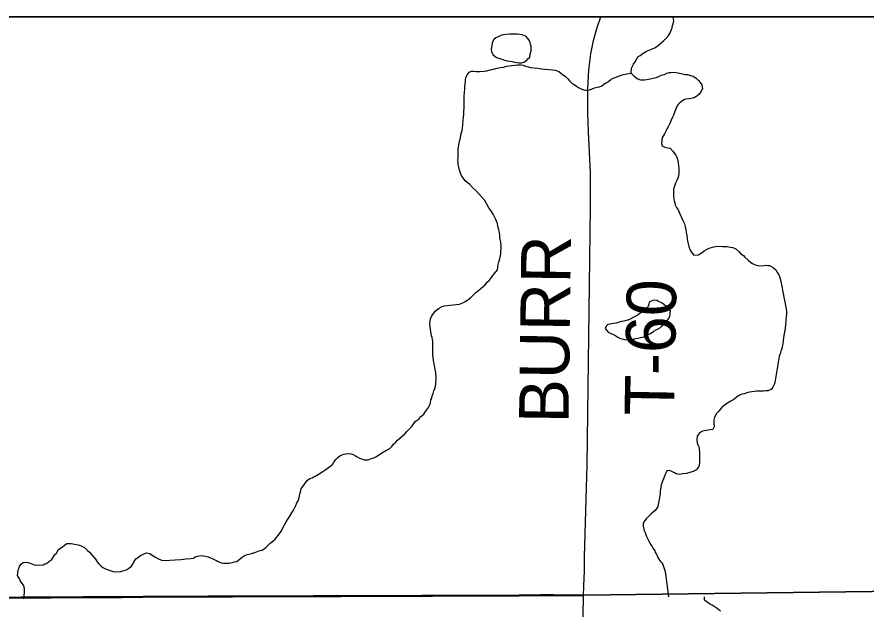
# Model space of a CAD drawing. Extents: x 0 to 34, y 0 to 22.
# Drawn here: x 3.195 to 4.168, y 20.221 to 20.9 of the extents above; entities that cross this region are included whole.
import ezdxf

# ---------------------------------------------------------------- set-up
doc = ezdxf.new("R2010")
doc.units = 0
for name, color, linetype in [('GM_X_Corporation', 7, 'Continuous'), ('GM_X_Minor_Lake', 7, 'Continuous'), ('GM_X_Minor_River', 7, 'Continuous'), ('GM_X_Township_Road', 7, 'Continuous'), ('GM_X_Township_Road_Text', 7, 'Continuous'), ('SH_Data', 7, 'Continuous')]:
    doc.layers.add(name, color=color, linetype=linetype)

msp = doc.modelspace()

# ---------------------------------------------------------------- linework, layer by layer
at = {"layer": 'GM_X_Corporation'}
for points in [[(7.88526, 20.89996), (2.1, 20.89996)], [(7.88526, 20.89996), (2.67133, 20.89996)], [(4.23527, 20.24193), (3.84431, 20.23677), (3.83537, 20.23691), (3.82602, 20.23702), (3.81005, 20.23712), (3.79513, 20.23712), (3.77046, 20.23676), (3.75805, 20.23671), (3.74563, 20.23667), (3.72077, 20.23656), (3.67105, 20.23646), (3.65864, 20.2364), (3.61523, 20.23629), (3.60009, 20.23626), (3.56599, 20.23605), (3.53492, 20.23598), (3.50078, 20.23579), (3.47907, 20.23578), (3.45731, 20.23576), (3.44179, 20.23571), (3.42316, 20.23562), (3.41385, 20.23562), (3.37656, 20.23558), (3.34551, 20.23546), (3.33933, 20.23533), (3.31461, 20.23489), (3.29289, 20.23498), (3.27112, 20.23493), (3.23381, 20.23452), (3.19962, 20.23446), (3.1561, 20.23368)], [(3.1561, 20.23368), (3.19962, 20.23446), (3.23381, 20.23452), (3.27112, 20.23493), (3.29289, 20.23498), (3.31461, 20.23489), (3.33933, 20.23533), (3.34551, 20.23546), (3.37656, 20.23558), (3.41385, 20.23562), (3.42316, 20.23562), (3.44179, 20.23571), (3.45731, 20.23576), (3.47907, 20.23578), (3.50078, 20.23579), (3.53492, 20.23598), (3.56599, 20.23605), (3.60009, 20.23626), (3.61523, 20.23629), (3.65864, 20.2364), (3.67105, 20.23646), (3.72077, 20.23656), (3.74563, 20.23667), (3.75805, 20.23671), (3.77046, 20.23676), (3.79513, 20.23712), (3.81005, 20.23712), (3.82602, 20.23702), (3.83537, 20.23691), (3.84431, 20.23677), (4.23527, 20.24193)], [(4.23527, 20.24193), (3.84431, 20.23677), (3.83537, 20.23691), (3.82602, 20.23702), (3.81005, 20.23712), (3.79513, 20.23712), (3.77046, 20.23676), (3.75805, 20.23671), (3.74563, 20.23667), (3.72077, 20.23656), (3.67105, 20.23646), (3.65864, 20.2364), (3.61523, 20.23629), (3.60009, 20.23626), (3.56599, 20.23605), (3.53492, 20.23598), (3.50078, 20.23579), (3.47907, 20.23578), (3.45731, 20.23576), (3.44179, 20.23571), (3.42316, 20.23562), (3.41385, 20.23562), (3.37656, 20.23558), (3.34551, 20.23546), (3.33933, 20.23533), (3.31461, 20.23489), (3.29289, 20.23498), (3.27112, 20.23493), (3.23381, 20.23452), (3.19962, 20.23446), (3.1561, 20.23368)], [(3.1561, 20.23368), (3.19962, 20.23446), (3.23381, 20.23452), (3.27112, 20.23493), (3.29289, 20.23498), (3.31461, 20.23489), (3.33933, 20.23533), (3.34551, 20.23546), (3.37656, 20.23558), (3.41385, 20.23562), (3.42316, 20.23562), (3.44179, 20.23571), (3.45731, 20.23576), (3.47907, 20.23578), (3.50078, 20.23579), (3.53492, 20.23598), (3.56599, 20.23605), (3.60009, 20.23626), (3.61523, 20.23629), (3.65864, 20.2364), (3.67105, 20.23646), (3.72077, 20.23656), (3.74563, 20.23667), (3.75805, 20.23671), (3.77046, 20.23676), (3.79513, 20.23712), (3.81005, 20.23712), (3.82602, 20.23702), (3.83537, 20.23691), (3.84431, 20.23677), (4.23527, 20.24193)]]:
    msp.add_lwpolyline(points, dxfattribs=at)
at = {"layer": 'GM_X_Minor_Lake'}
for points in [[(3.73984, 20.87132), (3.73843, 20.86296), (3.73884, 20.85992), (3.74077, 20.85652), (3.7446, 20.85352), (3.74727, 20.85278), (3.7507, 20.85168), (3.75261, 20.85094), (3.7568, 20.84984), (3.75985, 20.84911), (3.76252, 20.84876), (3.76518, 20.84802), (3.76785, 20.84767), (3.77013, 20.84731), (3.77317, 20.84734), (3.77583, 20.84813), (3.77885, 20.85007), (3.78073, 20.85237), (3.78262, 20.85353), (3.78333, 20.85773), (3.78444, 20.86078), (3.78439, 20.86611), (3.78361, 20.86838), (3.7832, 20.87066), (3.78204, 20.87331), (3.77857, 20.87746), (3.7759, 20.87858), (3.774, 20.87932), (3.77133, 20.88005), (3.76828, 20.8804), (3.76486, 20.88036), (3.76296, 20.88034), (3.75954, 20.88031), (3.75574, 20.87989), (3.7527, 20.87948), (3.75043, 20.87907), (3.74666, 20.87733)], [(3.74666, 20.87733), (3.744, 20.87596), (3.74136, 20.87403), (3.73986, 20.87135), (3.73984, 20.87132)], [(3.87244, 20.53863), (3.87664, 20.53677), (3.88008, 20.53491), (3.88352, 20.53266), (3.88658, 20.53117), (3.88886, 20.53081), (3.89153, 20.53008), (3.89495, 20.52973), (3.898, 20.52977), (3.90027, 20.53017), (3.90444, 20.53136), (3.9071, 20.53176), (3.90975, 20.53255), (3.91354, 20.53335), (3.91582, 20.53414), (3.91846, 20.53569), (3.92111, 20.53686), (3.92489, 20.53956), (3.92753, 20.54111), (3.9298, 20.54227), (3.93245, 20.54382), (3.93433, 20.54537), (3.93847, 20.54922), (3.93998, 20.55113), (3.94185, 20.55382), (3.94334, 20.5565), (3.94368, 20.5603), (3.94404, 20.56297), (3.9425, 20.56486), (3.94019, 20.5675), (3.93828, 20.56862), (3.93636, 20.57012), (3.93445, 20.57162), (3.93216, 20.57274), (3.93025, 20.57386), (3.92833, 20.57498), (3.92567, 20.57534), (3.92377, 20.57494), (3.92188, 20.57416), (3.91961, 20.57299), (3.91925, 20.5707), (3.91852, 20.56803), (3.91664, 20.56611), (3.914, 20.56418), (3.91174, 20.56149), (3.90947, 20.56033), (3.907, 20.55836)], [(3.907, 20.55836), (3.89776, 20.55336), (3.89511, 20.55219), (3.89321, 20.55179), (3.89056, 20.551), (3.8879, 20.55059), (3.88525, 20.5498), (3.88184, 20.549), (3.8788, 20.54859), (3.87652, 20.54819), (3.87463, 20.54779), (3.87235, 20.54738), (3.87047, 20.54546), (3.86936, 20.54279), (3.87244, 20.53863)]]:
    msp.add_lwpolyline(points, dxfattribs=at)
at = {"layer": 'GM_X_Minor_River'}
for points in [[(3.89912, 20.83534), (3.89944, 20.84143), (3.90055, 20.84373), (3.90167, 20.84602), (3.90355, 20.84871), (3.90541, 20.85215), (3.90691, 20.85445), (3.90918, 20.85562), (3.91257, 20.85831), (3.91484, 20.85948), (3.91673, 20.86064), (3.91862, 20.86142), (3.92052, 20.8622), (3.92241, 20.86298), (3.9243, 20.86376), (3.92619, 20.86455), (3.93034, 20.86763), (3.93637, 20.87302), (3.93863, 20.87533), (3.94089, 20.87764), (3.94314, 20.88109), (3.94425, 20.883), (3.94537, 20.88567), (3.94611, 20.88759), (3.94646, 20.89025), (3.94721, 20.89216), (3.94793, 20.89559), (3.94753, 20.89787), (3.94721, 20.89996)], [(3.70046, 20.74461), (3.7008, 20.74841), (3.70151, 20.75299), (3.70223, 20.75756), (3.70333, 20.76138), (3.70368, 20.76481), (3.70441, 20.76748), (3.70515, 20.76977), (3.7055, 20.77205), (3.70655, 20.7812), (3.70689, 20.78501), (3.70724, 20.78844), (3.70721, 20.79186), (3.70755, 20.79529), (3.70752, 20.79833), (3.7075, 20.801), (3.70746, 20.80442), (3.70743, 20.80709), (3.7074, 20.81013), (3.70776, 20.81203), (3.70775, 20.81394), (3.7081, 20.81623), (3.70846, 20.81813), (3.70844, 20.82041), (3.7088, 20.8227), (3.70914, 20.82613), (3.70912, 20.82803), (3.70985, 20.83146), (3.71134, 20.83414), (3.71322, 20.83683), (3.71587, 20.83799), (3.71815, 20.83764), (3.72158, 20.83729), (3.72538, 20.83733), (3.72993, 20.83776), (3.73335, 20.83818), (3.73714, 20.83936), (3.74132, 20.84016), (3.74548, 20.84135), (3.74928, 20.84215), (3.75269, 20.84257), (3.75611, 20.84336), (3.75914, 20.84377), (3.76218, 20.84419), (3.7656, 20.8446), (3.76864, 20.84502), (3.77244, 20.84505), (3.7751, 20.8447), (3.77777, 20.84359), (3.78082, 20.84286), (3.78349, 20.84212), (3.79148, 20.84107), (3.79377, 20.84071), (3.79643, 20.84036), (3.79948, 20.84001), (3.80442, 20.83968), (3.80861, 20.83934), (3.81203, 20.839), (3.81432, 20.83826), (3.81623, 20.83752), (3.81929, 20.83527), (3.82121, 20.83377), (3.82351, 20.83151), (3.8262, 20.82887), (3.8285, 20.82623), (3.83119, 20.8236), (3.83348, 20.82248), (3.83616, 20.82061), (3.83846, 20.81911), (3.84228, 20.81724), (3.84457, 20.81651), (3.84685, 20.81615), (3.84875, 20.81617), (3.85103, 20.81657), (3.85444, 20.81737), (3.85709, 20.81854), (3.86012, 20.81933), (3.86278, 20.81974), (3.86543, 20.82091), (3.86882, 20.82361), (3.87109, 20.82477), (3.87336, 20.82632), (3.87562, 20.82825), (3.87827, 20.8298), (3.88168, 20.83098), (3.88432, 20.83214), (3.8866, 20.83293), (3.88849, 20.83371), (3.89039, 20.83411), (3.89418, 20.83491), (3.89684, 20.83532), (3.89912, 20.83534), (3.90219, 20.83233), (3.90487, 20.83007), (3.90678, 20.82895), (3.90984, 20.82784), (3.91402, 20.82789), (3.91705, 20.8283), (3.92085, 20.8291), (3.92426, 20.8299), (3.92767, 20.83069)], [(3.92767, 20.83069), (3.9307, 20.83187), (3.93335, 20.83304), (3.93714, 20.83384), (3.93979, 20.83539), (3.94244, 20.83617), (3.94434, 20.83619), (3.94738, 20.83661), (3.95043, 20.83626), (3.95233, 20.8359), (3.95614, 20.83518), (3.95881, 20.83444), (3.96071, 20.83408), (3.96375, 20.83411), (3.96833, 20.83264), (3.97024, 20.8319), (3.97407, 20.82928), (3.97637, 20.82702), (3.97829, 20.82475), (3.97984, 20.82211), (3.98064, 20.81755), (3.97878, 20.8141), (3.9769, 20.81142), (3.97427, 20.80911), (3.97125, 20.80718), (3.96783, 20.80638), (3.96479, 20.80597), (3.96138, 20.80555), (3.95948, 20.80477), (3.95684, 20.80322), (3.9542, 20.80091), (3.95232, 20.79937), (3.9512, 20.79745), (3.95045, 20.79554), (3.94934, 20.79287), (3.94787, 20.78829), (3.94638, 20.78523), (3.94489, 20.78179), (3.94341, 20.77797), (3.94154, 20.77414), (3.93968, 20.77069), (3.93818, 20.7684), (3.93706, 20.7661), (3.93594, 20.76419), (3.93445, 20.76189), (3.93376, 20.75465), (3.93454, 20.75238), (3.9376, 20.75051), (3.94103, 20.74978), (3.94369, 20.74943), (3.94677, 20.74604), (3.94869, 20.74339), (3.95023, 20.74151), (3.9514, 20.73923), (3.95257, 20.73544), (3.95298, 20.73278), (3.95339, 20.72974), (3.9538, 20.7267), (3.95383, 20.72366), (3.95348, 20.72099), (3.95313, 20.71756), (3.9524, 20.71527), (3.95129, 20.7126), (3.94979, 20.70954), (3.94906, 20.70725), (3.94832, 20.70495), (3.94758, 20.70266), (3.94761, 20.70038), (3.94763, 20.69772), (3.94767, 20.69429), (3.94808, 20.69125), (3.94848, 20.68897), (3.94888, 20.68669), (3.94929, 20.68442), (3.95083, 20.68139), (3.95276, 20.67874), (3.95354, 20.67685), (3.95471, 20.6742), (3.9586, 20.66587), (3.96014, 20.66284), (3.96093, 20.6598), (3.96173, 20.65601), (3.96214, 20.65297), (3.96294, 20.64955), (3.96335, 20.64613), (3.96377, 20.64271), (3.96418, 20.63967), (3.96497, 20.63663), (3.96575, 20.63436), (3.96653, 20.63246), (3.96769, 20.63057), (3.96923, 20.62869), (3.97077, 20.6268), (3.97609, 20.62723), (3.97835, 20.62878), (3.98024, 20.62994), (3.98288, 20.63187), (3.98553, 20.63342), (3.98855, 20.63498), (3.99386, 20.63655), (3.99842, 20.63698)], [(3.67499, 20.47873), (3.67497, 20.48101), (3.67532, 20.48406), (3.67528, 20.48787), (3.67488, 20.49015), (3.67486, 20.49205), (3.67446, 20.49394), (3.67444, 20.49585), (3.67403, 20.49813), (3.67363, 20.50079), (3.67284, 20.50382), (3.67243, 20.50686), (3.67202, 20.50952), (3.67161, 20.51218), (3.67158, 20.51561), (3.67155, 20.51865), (3.67152, 20.52169), (3.67149, 20.52474), (3.67146, 20.52778), (3.67105, 20.53006), (3.67065, 20.53234), (3.67025, 20.53424), (3.66984, 20.5369), (3.66944, 20.53918), (3.66904, 20.54184), (3.66821, 20.5483), (3.66856, 20.55096), (3.66892, 20.55363), (3.67003, 20.55631), (3.67115, 20.55822), (3.67265, 20.56014), (3.67415, 20.56244), (3.67604, 20.56398), (3.67868, 20.56591), (3.68246, 20.56785), (3.68473, 20.56864), (3.68815, 20.56905), (3.69157, 20.56947), (3.69498, 20.56989), (3.69878, 20.57031), (3.7022, 20.57072), (3.70598, 20.57228), (3.70863, 20.57383), (3.71165, 20.57577), (3.71467, 20.57808), (3.71768, 20.58078), (3.72107, 20.58386), (3.72447, 20.58656), (3.7271, 20.58887), (3.72974, 20.59118), (3.73163, 20.59272), (3.73425, 20.59617), (3.73614, 20.59771), (3.73877, 20.60116), (3.74026, 20.60346), (3.74214, 20.60577), (3.74364, 20.60769), (3.7459, 20.60999), (3.74625, 20.61266), (3.7466, 20.61609), (3.74733, 20.61914), (3.74807, 20.62105), (3.74952, 20.62791), (3.74949, 20.63096), (3.74984, 20.63439), (3.74981, 20.63743), (3.74938, 20.64161), (3.74897, 20.64465), (3.74857, 20.64731), (3.74854, 20.64998), (3.74814, 20.65226), (3.74774, 20.65415), (3.74734, 20.65605), (3.74616, 20.66022), (3.74575, 20.66327), (3.74458, 20.66592), (3.74341, 20.66857), (3.74186, 20.6716), (3.7407, 20.67387), (3.738, 20.67802), (3.73569, 20.68105), (3.73336, 20.68521), (3.73104, 20.68937), (3.72796, 20.69314), (3.7245, 20.69729), (3.72104, 20.70106), (3.71759, 20.70407), (3.71413, 20.70784), (3.71107, 20.71009), (3.70877, 20.71197), (3.70722, 20.71423), (3.70452, 20.71801), (3.70336, 20.72104), (3.70218, 20.72446), (3.70138, 20.72787), (3.70059, 20.73091), (3.70057, 20.73357), (3.70016, 20.73585), (3.70052, 20.73852), (3.70049, 20.74118), (3.70046, 20.74461)], [(3.99842, 20.63698), (4.00374, 20.63666), (4.00868, 20.63671), (4.01287, 20.63599), (4.01554, 20.63564), (4.01897, 20.63415), (4.02242, 20.63115), (4.02473, 20.62851), (4.02779, 20.62625), (4.02933, 20.62437), (4.03317, 20.62098), (4.03624, 20.61835), (4.03815, 20.61723), (4.04044, 20.61611), (4.04235, 20.61537), (4.04425, 20.61501), (4.04654, 20.61465), (4.05147, 20.61509), (4.05375, 20.61549), (4.05566, 20.61513), (4.05755, 20.61515), (4.06176, 20.61253), (4.06483, 20.6099), (4.06677, 20.60649), (4.06831, 20.60423), (4.06909, 20.60233), (4.06988, 20.59968), (4.07066, 20.59702), (4.07146, 20.59284), (4.07226, 20.58943), (4.07267, 20.58639), (4.07346, 20.58297), (4.07389, 20.57879), (4.07508, 20.57347), (4.07588, 20.56891), (4.07668, 20.56512), (4.07709, 20.56208), (4.07712, 20.55941), (4.07677, 20.55599), (4.07644, 20.55142), (4.07611, 20.54685), (4.07539, 20.54265), (4.07467, 20.53846), (4.07395, 20.53465), (4.07359, 20.53198), (4.07325, 20.52855), (4.0729, 20.5255), (4.07254, 20.5236), (4.07218, 20.52131), (4.07145, 20.51864), (4.07071, 20.51673), (4.06998, 20.51368), (4.06886, 20.511), (4.06813, 20.50795), (4.06741, 20.50452), (4.06706, 20.50109), (4.06634, 20.4969), (4.06456, 20.48546), (4.06384, 20.48089), (4.06311, 20.4786), (4.06161, 20.47554), (4.05974, 20.47323), (4.05595, 20.47129), (4.05291, 20.47126), (4.05064, 20.47086), (4.04798, 20.47083), (4.04532, 20.4708), (4.04266, 20.47077), (4.04038, 20.47037), (4.03734, 20.46995), (4.03468, 20.46955), (4.03165, 20.46913), (4.02862, 20.46796), (4.02634, 20.46756), (4.02331, 20.46638), (4.01954, 20.46368), (4.01652, 20.46137), (4.01312, 20.45943), (4.00934, 20.45711), (4.00557, 20.4544), (4.00255, 20.45171), (3.99955, 20.44787), (3.99692, 20.44518), (3.99468, 20.44097), (3.99395, 20.43792), (3.99359, 20.43525), (3.99362, 20.43297), (3.9944, 20.43069), (3.99254, 20.42687), (3.9895, 20.42645), (3.98722, 20.42605), (3.98533, 20.42565), (3.98267, 20.42524), (3.98077, 20.42484), (3.97737, 20.42291), (3.97475, 20.41907), (3.97441, 20.41488), (3.97483, 20.41146), (3.97561, 20.40919), (3.97678, 20.40615), (3.9768, 20.40425)], [(3.43794, 20.27381), (3.44135, 20.27423), (3.44401, 20.27502), (3.44704, 20.27543), (3.44968, 20.27774), (3.45307, 20.28044), (3.45534, 20.28199), (3.45875, 20.28355), (3.46064, 20.28394), (3.46368, 20.28474), (3.46747, 20.28592), (3.47125, 20.28748), (3.47391, 20.28827), (3.4758, 20.28867), (3.47995, 20.29176), (3.48259, 20.29407), (3.48523, 20.29638), (3.48825, 20.29869), (3.49088, 20.301), (3.49239, 20.30292), (3.49389, 20.30484), (3.49539, 20.30676), (3.49688, 20.30906), (3.49838, 20.31136), (3.4995, 20.31403), (3.50136, 20.31748), (3.50361, 20.32092), (3.50548, 20.32399), (3.50773, 20.32744), (3.50997, 20.33127), (3.51184, 20.33433), (3.51333, 20.33739), (3.51445, 20.33968), (3.51555, 20.34274), (3.51705, 20.34504), (3.51779, 20.34733), (3.51889, 20.35077), (3.51962, 20.3542), (3.52036, 20.35687), (3.52072, 20.35878), (3.52634, 20.36683), (3.52784, 20.36874), (3.53048, 20.37067), (3.53313, 20.37146), (3.53502, 20.37262), (3.53805, 20.37418), (3.54145, 20.37612), (3.54447, 20.37805), (3.54787, 20.38037), (3.55051, 20.3823), (3.55353, 20.38461), (3.55655, 20.38693), (3.55804, 20.38961), (3.56029, 20.39267), (3.56255, 20.39498), (3.56481, 20.39653), (3.56708, 20.39769), (3.56974, 20.39848), (3.57201, 20.39889), (3.57505, 20.3993), (3.57772, 20.39894), (3.58038, 20.39821), (3.58306, 20.39672), (3.58497, 20.3956), (3.58764, 20.3941), (3.59108, 20.393), (3.59337, 20.39226), (3.59527, 20.39228), (3.59755, 20.3923), (3.60134, 20.39348), (3.60399, 20.39427), (3.60701, 20.39583), (3.61192, 20.3993), (3.61835, 20.40317), (3.62213, 20.40512), (3.62476, 20.40743), (3.62664, 20.41011), (3.62928, 20.41242), (3.63115, 20.41473), (3.63944, 20.42204), (3.6417, 20.42473), (3.64433, 20.42742), (3.64734, 20.43049), (3.65147, 20.43625), (3.656, 20.43896), (3.65674, 20.44087), (3.65938, 20.4428), (3.66127, 20.44434), (3.66239, 20.44625), (3.66426, 20.44894), (3.66651, 20.45201), (3.66763, 20.4543), (3.66874, 20.45736), (3.66947, 20.46079), (3.67059, 20.4627), (3.67094, 20.46537), (3.67206, 20.46804), (3.67279, 20.4711), (3.6739, 20.47377), (3.67463, 20.47644), (3.67499, 20.47873)], [(3.9768, 20.40425), (3.97721, 20.40121), (3.97725, 20.39703), (3.97729, 20.39284), (3.97733, 20.38904), (3.97698, 20.38599), (3.97624, 20.3837), (3.97361, 20.38062), (3.97021, 20.37869), (3.96642, 20.37751), (3.96225, 20.37632), (3.9577, 20.37589), (3.95466, 20.37548), (3.95237, 20.37584), (3.95047, 20.3762), (3.94856, 20.37732), (3.94474, 20.37918), (3.94245, 20.37992), (3.93979, 20.37951), (3.93905, 20.3776), (3.93756, 20.37454), (3.93608, 20.37034), (3.93497, 20.36766), (3.93423, 20.36537), (3.93349, 20.36346), (3.93313, 20.36118), (3.93278, 20.35851), (3.93242, 20.35622), (3.93208, 20.3528), (3.93028, 20.34288), (3.92956, 20.33869), (3.92844, 20.33677), (3.92656, 20.33409), (3.9243, 20.33216), (3.92204, 20.33024), (3.91978, 20.32793), (3.9179, 20.32601), (3.91602, 20.32447), (3.91452, 20.32255), (3.91264, 20.31948), (3.91268, 20.31606), (3.91387, 20.31113), (3.91503, 20.30885), (3.91582, 20.30658), (3.9166, 20.3043), (3.91776, 20.30203), (3.91931, 20.29901), (3.92047, 20.29673), (3.92164, 20.29446), (3.92318, 20.29258), (3.92434, 20.29031), (3.92627, 20.28766), (3.92667, 20.28577), (3.92821, 20.28388), (3.92977, 20.27933), (3.93209, 20.27593), (3.93401, 20.27405), (3.93517, 20.27215), (3.93752, 20.26533), (3.93831, 20.26153), (3.94189, 20.23488)], [(3.2026, 20.23286), (3.20335, 20.24055), (3.20331, 20.24397), (3.20291, 20.24663), (3.20213, 20.24852), (3.19943, 20.25192), (3.19827, 20.25381), (3.19749, 20.2557), (3.19555, 20.25949), (3.1959, 20.26254), (3.19625, 20.26597), (3.19737, 20.26826), (3.19773, 20.27017), (3.19998, 20.27285), (3.20187, 20.2744), (3.20529, 20.27481), (3.20719, 20.27445), (3.20986, 20.27372), (3.21367, 20.27223), (3.21558, 20.27149), (3.21748, 20.27152), (3.22014, 20.27116), (3.2247, 20.27159), (3.22659, 20.27275), (3.22849, 20.27315), (3.23264, 20.27624), (3.23491, 20.27779), (3.23827, 20.28353), (3.24015, 20.28507), (3.24239, 20.28928), (3.24504, 20.29121), (3.24692, 20.29237), (3.24918, 20.2943), (3.25183, 20.29623), (3.25677, 20.29628), (3.26058, 20.29556), (3.26477, 20.29446), (3.26706, 20.29372), (3.26897, 20.29298), (3.27202, 20.29149), (3.27548, 20.2881), (3.27778, 20.28622), (3.28008, 20.28358), (3.28239, 20.28094), (3.2847, 20.2783), (3.28663, 20.27528), (3.28817, 20.27339), (3.29124, 20.27), (3.29316, 20.2685), (3.29545, 20.26738), (3.29812, 20.26627), (3.30156, 20.26516), (3.30499, 20.26405), (3.30765, 20.2637), (3.31373, 20.26415), (3.316, 20.26493), (3.31866, 20.26572), (3.32055, 20.2665), (3.32319, 20.26805), (3.32621, 20.27037), (3.32733, 20.27228), (3.32883, 20.27458), (3.33107, 20.27841), (3.33296, 20.27957), (3.33636, 20.28227), (3.33938, 20.28382), (3.34128, 20.2846), (3.34355, 20.28539), (3.34698, 20.28466), (3.3508, 20.28204), (3.35272, 20.28091), (3.35616, 20.27905), (3.36036, 20.27719), (3.36454, 20.27685), (3.36986, 20.27691), (3.37632, 20.27736), (3.38278, 20.2778), (3.38885, 20.27863), (3.39417, 20.27907), (3.39721, 20.27948), (3.39909, 20.28102), (3.40174, 20.28181), (3.40364, 20.28221), (3.40592, 20.28223), (3.40821, 20.28187), (3.41087, 20.28152), (3.41392, 20.28079), (3.41659, 20.27968), (3.4185, 20.27894), (3.42079, 20.27782), (3.4227, 20.27708), (3.42461, 20.27596), (3.42881, 20.2741), (3.43147, 20.27375), (3.4349, 20.27378), (3.43794, 20.27381)], [(3.98285, 20.23502), (3.98286, 20.23173), (3.98362, 20.23135), (3.9878, 20.2283), (3.99008, 20.22678), (3.99198, 20.22602), (3.99425, 20.22449), (3.99767, 20.22183), (4.00147, 20.21878)]]:
    msp.add_lwpolyline(points, dxfattribs=at)
at = {"layer": 'GM_X_Township_Road'}
for points in [[(3.84452, 20.23621), (3.84485, 20.24758), (3.84533, 20.26467), (3.8456, 20.28092), (3.84838, 20.38639), (3.85245, 20.68143), (3.8522, 20.72176), (3.85013, 20.76833), (3.8492, 20.7899), (3.84915, 20.81774), (3.8504, 20.83938), (3.85269, 20.85781), (3.85566, 20.87296), (3.85994, 20.8878), (3.8643, 20.89996)], [(3.15631, 20.23313), (3.19984, 20.2339), (3.23403, 20.23397), (3.27133, 20.23438), (3.29311, 20.23443), (3.31483, 20.23433), (3.33955, 20.23477), (3.34572, 20.2349), (3.37677, 20.23503), (3.41407, 20.23507), (3.42338, 20.23507), (3.44201, 20.23516), (3.45753, 20.23521), (3.47928, 20.23523), (3.501, 20.23523), (3.53513, 20.23543), (3.56621, 20.23549), (3.60031, 20.23571), (3.61544, 20.23574), (3.65885, 20.23584), (3.67127, 20.23591), (3.72099, 20.236), (3.74585, 20.23612), (3.75826, 20.23615), (3.77067, 20.23621), (3.79534, 20.23657), (3.81027, 20.23657), (3.82624, 20.23646), (3.83559, 20.23636), (3.84452, 20.23621)], [(3.81701, 19.73137), (3.819, 19.75173), (3.83464, 19.86415), (3.84301, 19.95836), (3.84395, 20.00168), (3.84261, 20.04424), (3.84206, 20.09478), (3.84452, 20.23621)]]:
    msp.add_lwpolyline(points, dxfattribs=at)
at = {"layer": 'SH_Data'}
msp.add_line((2.1, 20.89996), (8.9, 20.89996), dxfattribs=at)

# ---------------------------------------------------------------- texts
at = {"layer": 'GM_X_Township_Road_Text'}
for s, rotation, p in [('BURR', 89.24323, (3.82716, 20.43376)), ('T-60', 88.93965, (3.94812, 20.44247))]:
    msp.add_text(s, height=0.056818, rotation=rotation, dxfattribs=at).set_placement(p)

doc.saveas('drawing.dxf')
